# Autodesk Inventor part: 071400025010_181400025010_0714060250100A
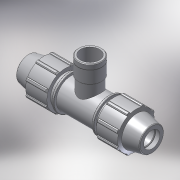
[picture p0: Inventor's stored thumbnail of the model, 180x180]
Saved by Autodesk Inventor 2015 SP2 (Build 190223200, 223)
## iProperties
Created: 2017-02
Part Number: 071400025010_181400025010_0714060250100A
Material: PVC-Piping
Description: PLASSON TEE WITH THREADED FEMALE OFFTAKE 25-1"-25
Document SubType Name: Modeling
Designer: KIM
Mass: 92.6774 g
Surface Area: 199.44 cm^2
Volume: 66.1981 cm^3
Density: 1.4 g/cm^3
Appearance: Smooth - White
Author: KIM
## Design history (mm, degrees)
derived "07140.ipt"
feature "Solid1::07140.ipt"
feature "Solid2::07140.ipt"
tag "TaggingFeature1"
body "Solid1"
other parameters: "d2" = 25, "d4" = 6.58333, "d5" = 18.96, "d7" = 54, "d11" = 2.63333, "d13" = 120 deg, "d14" = 37.5, "d15" = 12 deg, "d16" = 46.98, "d18" = 1.25, "d19" = 35 deg, "d20" = 17.5 deg, "d21" = 50.22, "d23" = 0, "d25" = 360 deg, "d27" = 1.08, "d33" = 0.5, "d42" = 28.44, "d43" = 1.62, "d46" = 0.75, "d68" = 4.74, "d72" = 53, "d76" = 30.291, "d80" = 0.90873, "d91" = 40.5, "d93" = 58, "d95" = 22.5, "d112" = 21, "d115" = 37.86375, "d116" = 135 deg, "d117" = 34.83465, "d118" = 158, "d119" = 22.5, "d121" = 0, "d122" = 22.5, "d124" = 0, "d128" = 0, "d129" = 2.5, "d130" = 6.3, "d131" = 0.3, "d132" = 0.3, "d133" = 37.86375, "d_" = 25, "E_" = 54, "A_" = 53, "l_" = 58, "l_2" = 21, "Rp_" = 30.291, "H_" = 158
